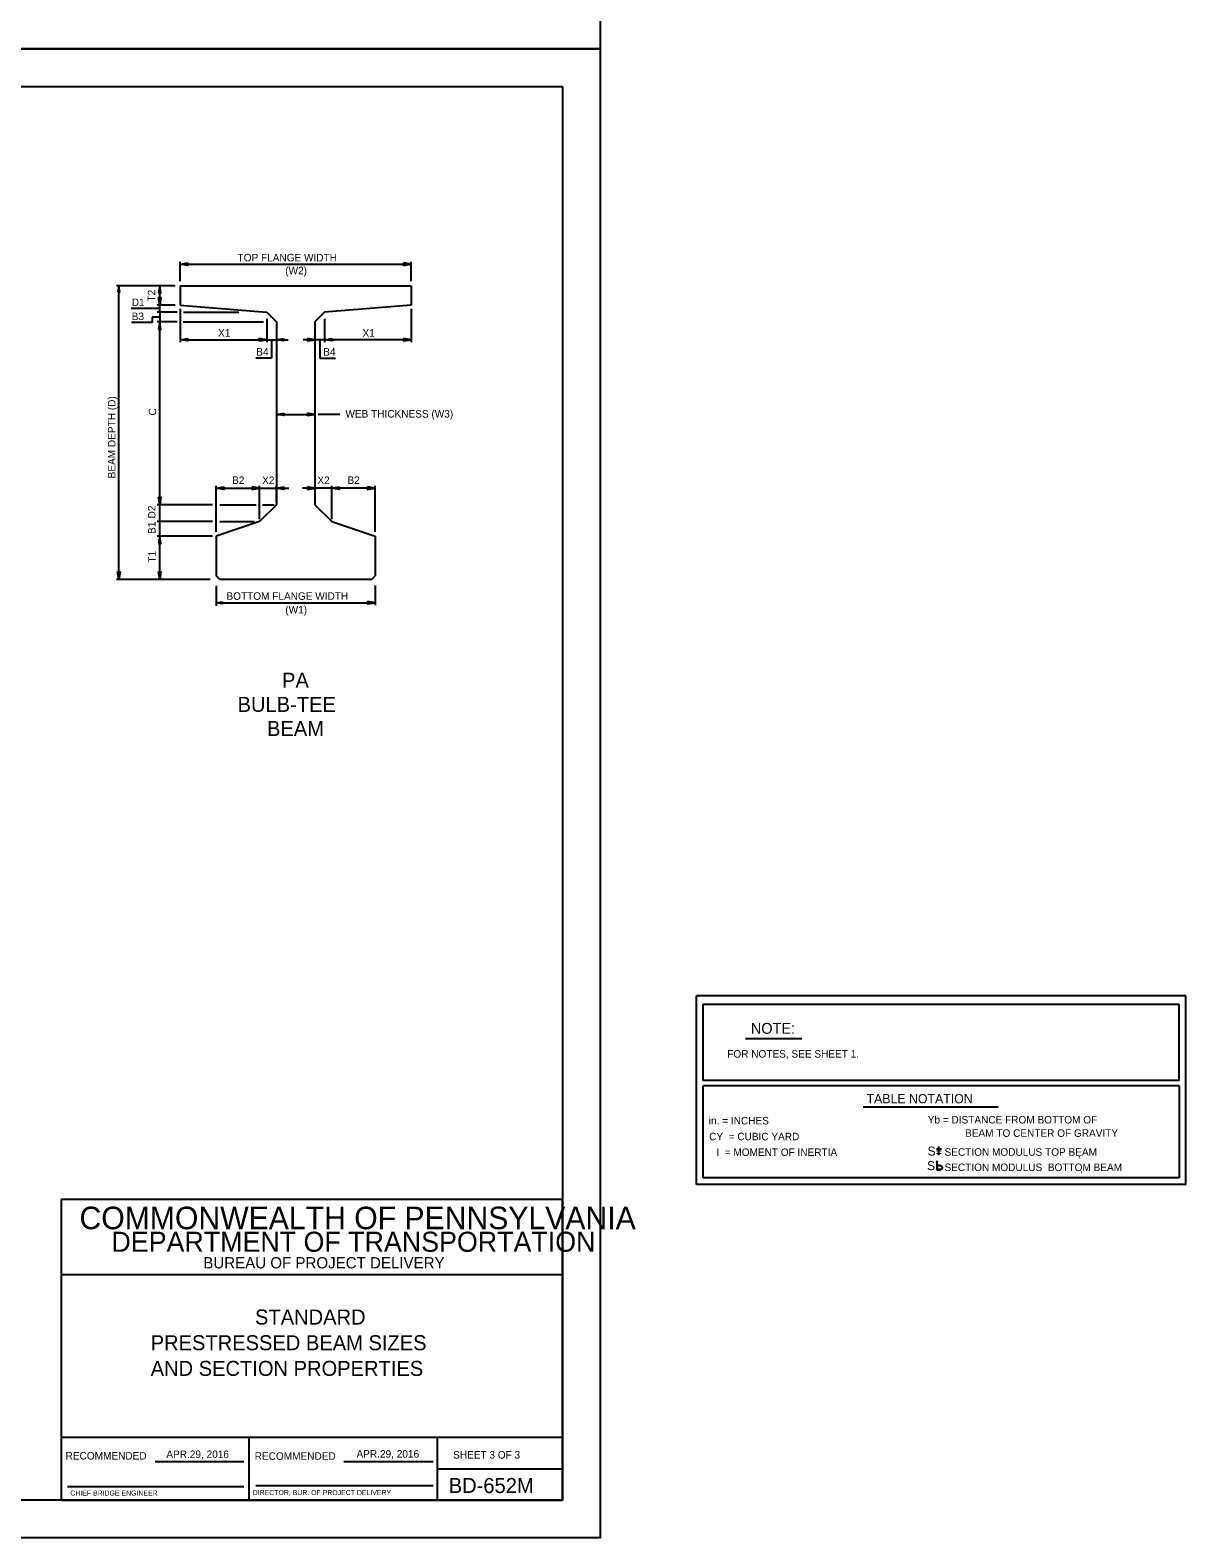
# Model space of a CAD drawing. Extents: x 635698 to 639877, y 296617 to 300175.
# Drawn here: x 639416 to 639877, y 298258 to 298859 of the extents above; entities that cross this region are included whole.
import ezdxf

# ---------------------------------------------------------------- set-up
doc = ezdxf.new("R2010")
doc.units = 0
for name, color, linetype in [('1', 7, 'Continuous'), ('2', 7, 'Continuous'), ('3', 7, 'Continuous'), ('PLT-BNDY', 7, 'Continuous')]:
    doc.layers.add(name, color=color, linetype=linetype)

# ---------------------------------------------------------------- blocks, each defined once
blk = doc.blocks.new('SEC8EN')
at = {"layer": '3'}
for p, q in [((0, 0), (18.288, 0)), ((0, 0), (0, -1.524)), ((18.288, 0), (18.288, -1.524)), ((0, -1.524), (6.858, -2.0955)), ((6.858, -2.0955), (7.62, -2.8575)), ((11.43, -2.0955), (10.668, -2.8575)), ((18.288, -1.524), (11.43, -2.0955)), ((7.62, -2.8575), (7.62, -17.3355)), ((10.668, -2.8575), (10.668, -17.3355)), ((7.62, -17.3355), (6.2865, -18.669)), ((10.668, -17.3355), (12.0015, -18.669)), ((6.2865, -18.669), (2.8575, -19.812)), ((12.0015, -18.669), (15.4305, -19.812)), ((2.8575, -19.812), (2.8575, -22.95525)), ((15.4305, -19.812), (15.4305, -22.95525)), ((3.14325, -23.241), (2.8575, -22.95525)), ((15.14475, -23.241), (3.14325, -23.241)), ((15.14475, -23.241), (15.4305, -22.95525))]:
    blk.add_line(p, q, dxfattribs=at)

msp = doc.modelspace()

# ---------------------------------------------------------------- linework, layer by layer
at = {"layer": '1'}
for p, q in [((639514.13, 298741.96), (639514.13, 298734.84)), ((639514.13, 298705.96), (639514.13, 298705.06)), ((639529.5, 298705.9), (639529.5, 298705.06)), ((639514.13, 298670.92), (639514.13, 298677.53)), ((639681.77, 298398.73), (639681.77, 298474.03)), ((639684.41, 298440.24), (639684.41, 298470.78)), ((639874.47, 298440.24), (639874.47, 298470.78)), ((639877.11, 298398.73), (639877.11, 298474.03)), ((639874.47, 298440.24), (639684.41, 298440.24)), ((639874.47, 298438.12), (639684.41, 298438.12)), ((639684.41, 298401.37), (639684.41, 298438.12)), ((639874.47, 298438.12), (639874.47, 298401.37)), ((639748.37, 298429.8), (639802.16, 298429.8)), ((639877.11, 298398.73), (639681.77, 298398.73)), ((639874.47, 298401.37), (639684.41, 298401.37))]:
    msp.add_line(p, q, dxfattribs=at)
at = {"layer": '2'}
for p, q in [((638842.3, 298836.8), (639628.3, 298836.8)), ((639628.3, 298836.8), (639628.3, 298272.8)), ((639475.73, 298759.12), (639475.73, 298766.89)), ((639477.65, 298765.93), (639565.98, 298765.93)), ((639567.9, 298759.12), (639567.9, 298766.89)), ((639471.89, 298757.33), (639450.3, 298757.33)), ((639451.26, 298642.11), (639451.26, 298755.41)), ((639473.77, 298757.33), (639452.61, 298757.33)), ((639467.56, 298749.65), (639467.56, 298757.33)), ((639459.92, 298748.21), (639456.23, 298748.21)), ((639467.56, 298748.2), (639459.92, 298748.21)), ((639473.77, 298749.65), (639466.6, 298749.65)), ((639473.77, 298749.65), (639466.6, 298749.65)), ((639467.56, 298746.77), (639467.56, 298749.65)), ((639475.73, 298748.07), (639475.73, 298734.84)), ((639567.9, 298748.07), (639567.9, 298734.84)), ((639464.52, 298742.69), (639456.26, 298742.69)), ((639467.56, 298744.84), (639464.52, 298744.85)), ((639464.52, 298744.85), (639464.52, 298742.69)), ((639474.48, 298746.77), (639466.6, 298746.77)), ((639474.48, 298746.77), (639466.6, 298746.77)), ((639474.48, 298742.92), (639466.6, 298742.92)), ((639474.48, 298742.92), (639466.6, 298742.92)), ((639467.56, 298746.77), (639467.56, 298742.92)), ((639467.56, 298671.88), (639467.56, 298741)), ((639476.94, 298742.9), (639509.01, 298742.9)), ((639477.06, 298746.74), (639499.19, 298746.74)), ((639510.29, 298744.2), (639510.29, 298734.84)), ((639533.34, 298744.2), (639533.34, 298734.84)), ((639477.65, 298735.8), (639508.37, 298735.8)), ((639508.37, 298735.8), (639506.45, 298735.8)), ((639510.29, 298735.8), (639514.13, 298735.8)), ((639510.29, 298735.8), (639514.13, 298735.8)), ((639512.21, 298735.8), (639512.21, 298728.46)), ((639516.05, 298735.8), (639518.87, 298735.8)), ((639527.58, 298735.8), (639524.76, 298735.8)), ((639533.34, 298735.8), (639529.5, 298735.8)), ((639533.34, 298735.8), (639529.5, 298735.8)), ((639531.42, 298735.8), (639531.42, 298728.46)), ((639565.98, 298735.8), (639535.26, 298735.8)), ((639535.26, 298735.8), (639537.18, 298735.8)), ((639512.21, 298728.46), (639505.95, 298728.46)), ((639531.42, 298728.46), (639537.68, 298728.46)), ((639514.13, 298706.02), (639527.58, 298706.02)), ((639539.5, 298706.02), (639530.75, 298706.02)), ((639490.13, 298659.13), (639490.13, 298677.53)), ((639490.13, 298676.57), (639507.41, 298676.57)), ((639507.41, 298664.19), (639507.41, 298677.53)), ((639507.41, 298676.57), (639519.04, 298676.57)), ((639536.22, 298676.57), (639524.59, 298676.57)), ((639536.22, 298664.19), (639536.22, 298677.53)), ((639553.5, 298676.57), (639536.22, 298676.57)), ((639553.5, 298659.13), (639553.5, 298677.53)), ((639488.65, 298669.96), (639466.6, 298669.96)), ((639488.65, 298669.96), (639466.6, 298669.96)), ((639467.56, 298663.23), (639467.56, 298669.96)), ((639491.61, 298669.96), (639506.1, 298669.96)), ((639508.58, 298669.96), (639513.23, 298669.96)), ((639488.65, 298663.23), (639466.6, 298663.23)), ((639488.65, 298663.23), (639466.6, 298663.23)), ((639467.56, 298657.47), (639467.56, 298663.23)), ((639491.61, 298663.23), (639505.27, 298663.23)), ((639486.29, 298657.47), (639466.6, 298657.47)), ((639488.67, 298657.47), (639466.6, 298657.47)), ((639467.56, 298642.11), (639467.56, 298655.55)), ((639487.73, 298640.19), (639450.3, 298640.19)), ((639487.73, 298640.19), (639452.61, 298640.19)), ((639490.13, 298637.56), (639490.13, 298629.68)), ((639553.5, 298637.79), (639553.5, 298629.92)), ((639492.05, 298630.88), (639551.58, 298630.88)), ((639877.11, 298474.03), (639681.77, 298474.03)), ((639684.41, 298470.78), (639874.47, 298470.78)), ((639701.36, 298457.03), (639723.78, 298457.03)), ((639628.3, 298392.8), (639428.3, 298392.8)), ((639428.3, 298392.8), (639428.3, 298272.8)), ((639628.3, 298272.8), (639628.3, 298392.8)), ((639628.3, 298362.8), (639428.3, 298362.8)), ((639628.3, 298297.8), (639428.3, 298297.8)), ((639503.3, 298272.8), (639503.3, 298297.8)), ((639578.3, 298297.8), (639578.3, 298272.8)), ((639465.71, 298288.3), (639501.09, 298288.3)), ((639541.09, 298288.3), (639576.73, 298288.3)), ((639578.3, 298285.3), (639628.3, 298285.3)), ((639430.8, 298278.3), (639501.09, 298278.3)), ((639505.92, 298278.68), (639576.73, 298278.68)), ((639628.3, 298272.8), (638842.3, 298272.8)), ((639428.3, 298272.8), (639628.3, 298272.8))]:
    msp.add_line(p, q, dxfattribs=at)
for points in [[(639478.73, 298766.43), (639478.73, 298765.43), (639475.73, 298765.93), (639475.73, 298765.93)], [(639564.9, 298766.43), (639564.9, 298765.43), (639567.9, 298765.93), (639567.9, 298765.93)], [(639450.86, 298754.93), (639451.66, 298754.93), (639451.26, 298757.33), (639451.26, 298757.33)], [(639467.06, 298754.33), (639468.06, 298754.33), (639467.56, 298757.33), (639467.56, 298757.33)], [(639467.06, 298752.65), (639468.06, 298752.65), (639467.56, 298749.65), (639467.56, 298749.65)], [(639467.06, 298739.92), (639468.06, 298739.92), (639467.56, 298742.92), (639467.56, 298742.92)], [(639478.73, 298736.3), (639478.73, 298735.3), (639475.73, 298735.8), (639475.73, 298735.8)], [(639507.29, 298736.3), (639507.29, 298735.3), (639510.29, 298735.8), (639510.29, 298735.8)], [(639517.03, 298736.3), (639517.03, 298735.3), (639514.03, 298735.8), (639514.03, 298735.8)], [(639526.6, 298736.3), (639526.6, 298735.3), (639529.6, 298735.8), (639529.6, 298735.8)], [(639536.34, 298736.3), (639536.34, 298735.3), (639533.34, 298735.8), (639533.34, 298735.8)], [(639564.9, 298736.3), (639564.9, 298735.3), (639567.9, 298735.8), (639567.9, 298735.8)], [(639517.13, 298706.52), (639517.13, 298705.52), (639514.13, 298706.02), (639514.13, 298706.02)], [(639526.5, 298706.52), (639526.5, 298705.52), (639529.5, 298706.02), (639529.5, 298706.02)], [(639493.13, 298677.07), (639493.13, 298676.07), (639490.13, 298676.57), (639490.13, 298676.57)], [(639504.41, 298677.07), (639504.41, 298676.07), (639507.41, 298676.57), (639507.41, 298676.57)], [(639517.13, 298677.07), (639517.13, 298676.07), (639514.13, 298676.57), (639514.13, 298676.57)], [(639526.5, 298677.07), (639526.5, 298676.07), (639529.5, 298676.57), (639529.5, 298676.57)], [(639539.22, 298677.07), (639539.22, 298676.07), (639536.22, 298676.57), (639536.22, 298676.57)], [(639550.5, 298677.07), (639550.5, 298676.07), (639553.5, 298676.57), (639553.5, 298676.57)], [(639467.06, 298672.96), (639468.06, 298672.96), (639467.56, 298669.96), (639467.56, 298669.96)], [(639467.06, 298654.47), (639468.06, 298654.47), (639467.56, 298657.47), (639467.56, 298657.47)], [(639450.76, 298643.19), (639451.76, 298643.19), (639451.26, 298640.19), (639451.26, 298640.19)], [(639467.06, 298643.19), (639468.06, 298643.19), (639467.56, 298640.19), (639467.56, 298640.19)], [(639492.53, 298631.28), (639492.53, 298630.48), (639490.13, 298630.88), (639490.13, 298630.88)], [(639550.5, 298631.38), (639550.5, 298630.38), (639553.5, 298630.88), (639553.5, 298630.88)]]:
    msp.add_lwpolyline(points, close=True, dxfattribs=at)
for points in [[(639779.54, 298412.83), (639777.64, 298412.83)], [(639778.58, 298410.42), (639778.58, 298413.87)], [(639777.86, 298404.47), (639777.86, 298408.16)], [(639777.89, 298406.3), (639778.26, 298406.51), (639778.63, 298406.55), (639778.95, 298406.51), (639779.25, 298406.37), (639779.43, 298406.25), (639779.62, 298406.05), (639779.71, 298405.86), (639779.8, 298405.7), (639779.8, 298405.27), (639779.66, 298405.01), (639779.55, 298404.88), (639779.2, 298404.62), (639778.97, 298404.51), (639778.63, 298404.46), (639778.17, 298404.51), (639777.89, 298404.69)]]:
    msp.add_lwpolyline(points, dxfattribs=at)
for centre, start, end in [((639467.56, 298746.77), 0, 180), ((639467.56, 298746.77), 180, 0), ((639467.56, 298663.23), 0, 180), ((639467.56, 298663.23), 180, 0)]:
    msp.add_arc(centre, 0.12, start, end, dxfattribs=at)
at = {"layer": 'PLT-BNDY'}
for points in [[(638802.3, 299445.8), (639643.3, 299445.8), (639643.3, 298851.8), (638802.3, 298851.8)], [(638802.3, 298851.8), (639643.3, 298851.8), (639643.3, 298257.8), (638802.3, 298257.8)]]:
    msp.add_lwpolyline(points, close=True, dxfattribs=at)

# ---------------------------------------------------------------- block references
at = {"layer": '2', "xscale": 5.040000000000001, "yscale": 5.040000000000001}
msp.add_blockref('SEC8EN', (639475.73, 298757.33), dxfattribs=at)

# ---------------------------------------------------------------- texts
at = {"layer": '1'}
for s, height, p in [('CY  = CUBIC YARD', 2.9979, (639686.86, 298416.41)), ('I  = MOMENT OF INERTIA', 2.9979, (639689.73, 298410.15)), (',', 3, (639834, 298409.68)), (',', 3, (639834.83, 298403.68)), ('APR.29, 2016', 3, (639470.22, 298289.65)), ('APR.29, 2016', 3, (639546.12, 298289.8))]:
    msp.add_text(s, height=height, dxfattribs=at).set_placement(p)
at = {"layer": '2'}
for s, height, p in [('TOP FLANGE WIDTH', 3, (639498.64, 298767.06)), ('(W2)', 3, (639517.67, 298761.9)), ('D1', 3, (639456.41, 298749.24)), ('B3', 3, (639456.4, 298743.63)), ('X1', 3, (639490.85, 298737.02)), ('X1', 3, (639548.5, 298737.02)), ('B4', 3, (639506.12, 298729.44)), ('B4', 3, (639532.83, 298729.44)), ('WEB THICKNESS (W3)', 3, (639541.69, 298704.75)), ('B2', 3, (639496.46, 298678.26)), ('X2', 3, (639508.46, 298678.23)), ('X2', 3, (639530.5, 298678.23)), ('B2', 3, (639542.49, 298678.26)), ('BOTTOM FLANGE WIDTH', 3.0004, (639494.21, 298632.03)), ('(W1)', 3, (639517.7, 298626.59)), ('PA', 6, (639516.39, 298596.95)), ('BULB-TEE', 6, (639498.64, 298587.32)), ('BEAM', 6, (639510.38, 298577.7)), ('NOTE:', 4.331, (639703.48, 298458.9)), ('    FOR NOTES, SEE SHEET 1.', 3, (639689.61, 298449.39)), ('S', 3.6, (639774.01, 298410.3)), ('S', 3.6, (639773.82, 298404.49)), ('COMMONWEALTH OF PENNSYLVANIA', 9, (639435.55, 298380.93)), ('DEPARTMENT OF TRANSPORTATION', 8.0002, (639448.3, 298371.93)), ('BUREAU OF PROJECT DELIVERY', 4.5, (639484.96, 298365.3)), ('STANDARD', 6, (639505.6, 298342.9)), ('PRESTRESSED BEAM SIZES', 6, (639463.95, 298332.65)), ('AND SECTION PROPERTIES', 6, (639463.95, 298322.41)), ('SHEET 3 OF 3', 3, (639584.67, 298289.43)), ('BD-652M', 6, (639582.92, 298275.68)), ('CHIEF BRIDGE ENGINEER', 2.0002, (639431.89, 298274.68)), ('  DIRECTOR, BUR. OF PROJECT DELIVERY', 2.0002, (639503.15, 298274.86))]:
    msp.add_text(s, height=height, dxfattribs=at).set_placement(p)
for s, height, rotation, p in [('T2', 3, 90, (639465.76, 298751.05)), ('BEAM DEPTH (D)', 3.0004, 90, (639449.91, 298680.49)), ('C', 3, 90, (639466.19, 298705.56)), ('D2', 3, 90, (639465.88, 298664.5)), ('B1', 3, 90, (639465.93, 298658.32)), ('T1', 3, 90, (639466, 298646.91)), ('RECOMMENDED', 3, 360, (639430.02, 298289.05)), ('RECOMMENDED', 3, 360, (639505.49, 298288.93))]:
    msp.add_text(s, height=height, rotation=rotation, dxfattribs=at).set_placement(p)
at = {"layer": '3'}
for s, height, p in [('TABLE NOTATION', 3.6796, (639749.66, 298431.17)), ('in. = INCHES', 3, (639686.72, 298422.74)), ('Yb = DISTANCE FROM BOTTOM OF', 3, (639774.09, 298423.12)), ('BEAM TO CENTER OF GRAVITY', 3, (639788.99, 298417.79)), ('   = SECTION MODULUS TOP BEAM', 3, (639774, 298410.23)), ('   = SECTION MODULUS  BOTTOM BEAM', 3, (639773.98, 298404.13))]:
    msp.add_text(s, height=height, dxfattribs=at).set_placement(p)

doc.saveas('drawing.dxf')
